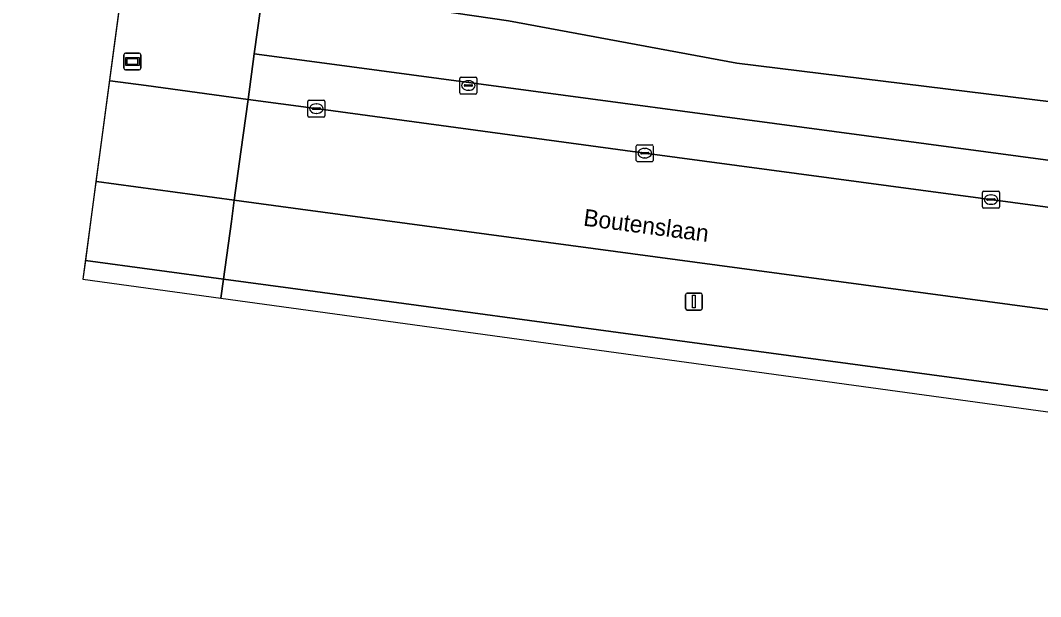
# Model space of a CAD drawing. Extents: x 161139 to 161601, y 381708 to 382245.
# Drawn here: x 161255.1 to 161315.4, y 381708.6 to 381742.6 of the extents above; entities that cross this region are included whole.
import ezdxf

# ---------------------------------------------------------------- set-up
doc = ezdxf.new("R2010")
doc.units = 0
for name, color, linetype in [('IMGEO_Berm_groen', 7, 'Continuous'), ('IMGEO_Dek', 7, 'Continuous'), ('IMGEO_Informatiebord', 7, 'Continuous'), ('IMGEO_Kolk', 7, 'Continuous'), ('IMGEO_Lichtmast', 7, 'Continuous'), ('IMGEO_Openbare_ruimte_label', 7, 'Continuous'), ('IMGEO_Rijbaan_regionaal_gesloten', 7, 'Continuous'), ('IMGEO_Rioolput', 7, 'Continuous'), ('IMGEO_Waterloop', 7, 'Continuous')]:
    doc.layers.add(name, color=color, linetype=linetype)

msp = doc.modelspace()

# ---------------------------------------------------------------- linework, layer by layer
at = {"layer": 'IMGEO_Berm_groen'}
for points in [[(161260.408, 381739.045), (161260.451, 381739.039), (161262.58, 381738.75), (161268.596, 381737.935), (161268.964, 381740.632), (161269.503, 381744.577), (161269.509, 381744.62), (161269.019, 381744.662), (161268.53, 381744.705), (161267.855, 381744.799), (161263.559, 381745.382), (161263.146, 381745.438), (161261.357, 381745.672), (161261.293, 381745.681)], [(161283.989, 381742.578), (161279.785, 381743.184), (161278.93, 381743.302), (161273.313, 381744.063), (161270.564, 381744.435), (161269.503, 381744.577), (161268.964, 381740.632), (161272.807, 381740.117), (161390.902, 381724.29), (161397.032, 381723.44), (161397.056, 381723.621), (161396.92, 381724.62), (161396.612, 381725.505), (161395.912, 381726.127), (161393.777, 381727.484), (161392.598, 381727.943), (161386.682, 381728.916), (161372.991, 381730.97), (161355.514, 381733.064), (161324.679, 381736.724), (161297.467, 381740.089)], [(161272.807, 381740.117), (161268.964, 381740.632), (161268.596, 381737.935), (161272.46, 381737.411), (161292.031, 381734.758), (161396.904, 381720.692), (161397.234, 381723.065), (161397.244, 381723.227), (161397.008, 381723.257), (161397.032, 381723.44), (161390.902, 381724.29)], [(161258.99, 381728.417), (161259, 381728.416), (161267.146, 381727.315), (161267.61, 381730.715), (161267.783, 381731.983), (161259.637, 381733.078), (161259.612, 381733.081)], [(161271.697, 381731.457), (161267.783, 381731.983), (161267.61, 381730.715), (161267.146, 381727.315), (161271.097, 381726.781), (161295.256, 381723.516), (161341.985, 381717.206), (161388.748, 381710.952), (161395.417, 381710.059), (161396.075, 381714.735)]]:
    msp.add_lwpolyline(points, close=True, dxfattribs=at)
msp.add_lwpolyline([(161269.509, 381744.62), (161269.503, 381744.577), (161270.564, 381744.435), (161273.313, 381744.063), (161278.93, 381743.302), (161279.785, 381743.184), (161283.989, 381742.578), (161297.467, 381740.089), (161324.679, 381736.724), (161355.514, 381733.064), (161372.991, 381730.97), (161386.682, 381728.916), (161392.598, 381727.943), (161393.777, 381727.484), (161395.912, 381726.127), (161396.612, 381725.505), (161396.92, 381724.62), (161397.056, 381723.621), (161397.032, 381723.44), (161397.008, 381723.257), (161397.244, 381723.227), (161397.255, 381723.409), (161401.979, 381722.847), (161404.437, 381741.198)], dxfattribs=at)
at = {"layer": 'IMGEO_Dek'}
msp.add_lwpolyline([(161266.992, 381726.19), (161267.146, 381727.315), (161267.61, 381730.715), (161267.783, 381731.983), (161268.174, 381734.839), (161268.596, 381737.935), (161268.964, 381740.632), (161269.503, 381744.577), (161270.244, 381750), (161270.446, 381751.48), (161270.863, 381754.533), (161270.924, 381754.975), (161262.781, 381756.092), (161262.685, 381756.105), (161258.842, 381727.311)], close=True, dxfattribs=at)
at = {"layer": 'IMGEO_Informatiebord'}
for p, q in [((161261.264, 381739.778), (161261.264, 381740.578)), ((161261.264, 381740.578), (161261.264, 381739.778)), ((161261.364, 381740.678), (161262.154, 381740.678)), ((161262.154, 381740.678), (161261.364, 381740.678)), ((161262.254, 381740.578), (161262.254, 381739.778)), ((161262.254, 381739.778), (161262.254, 381740.578)), ((161262.154, 381739.678), (161261.364, 381739.678)), ((161261.364, 381739.678), (161262.154, 381739.678))]:
    msp.add_line(p, q, dxfattribs=at)
for points in [[(161261.365, 381740.41), (161262.153, 381740.41), (161262.153, 381739.946), (161261.365, 381739.946), (161261.365, 381740.41)], [(161261.43, 381740.345), (161261.43, 381740.011), (161262.088, 381740.011), (161262.088, 381740.345), (161261.43, 381740.345)]]:
    msp.add_lwpolyline(points, dxfattribs=at)
for centre, start, end in [((161261.364, 381740.578), 90, 180), ((161261.364, 381740.578), 90, 180), ((161262.154, 381740.578), 0, 90), ((161262.154, 381740.578), 360, 90), ((161261.364, 381739.778), 180, 270), ((161261.364, 381739.778), 180, 270), ((161262.154, 381739.778), 270, 0), ((161262.154, 381739.778), 270, 0)]:
    msp.add_arc(centre, 0.1, start, end, dxfattribs=at)
at = {"layer": 'IMGEO_Kolk'}
for p, q in [((161272.131, 381736.967), (161272.131, 381737.819)), ((161272.206, 381737.893), (161273.058, 381737.893)), ((161272.619, 381737.673), (161272.644, 381737.673)), ((161273.132, 381737.819), (161273.132, 381736.967)), ((161273.058, 381736.893), (161272.206, 381736.893)), ((161272.39, 381737.387), (161272.39, 381737.399)), ((161272.828, 381737.35), (161272.43, 381737.35)), ((161272.433, 381737.436), (161272.831, 381737.436)), ((161272.642, 381737.113), (161272.617, 381737.113)), ((161272.874, 381737.399), (161272.874, 381737.387)), ((161291.53, 381734.332), (161291.53, 381735.184)), ((161291.605, 381735.258), (161292.457, 381735.258)), ((161292.531, 381735.184), (161292.531, 381734.332)), ((161291.789, 381734.752), (161291.789, 381734.764)), ((161292.227, 381734.715), (161291.829, 381734.715)), ((161291.832, 381734.801), (161292.23, 381734.801)), ((161292.041, 381734.478), (161292.016, 381734.478)), ((161292.018, 381735.038), (161292.043, 381735.038)), ((161292.273, 381734.764), (161292.273, 381734.752)), ((161292.457, 381734.258), (161291.605, 381734.258)), ((161311.983, 381731.591), (161311.983, 381732.443)), ((161312.058, 381732.517), (161312.91, 381732.517)), ((161312.285, 381732.06), (161312.683, 381732.06)), ((161312.471, 381732.297), (161312.496, 381732.297)), ((161312.984, 381732.443), (161312.984, 381731.591)), ((161312.91, 381731.517), (161312.058, 381731.517)), ((161312.242, 381732.011), (161312.242, 381732.023)), ((161312.68, 381731.974), (161312.282, 381731.974)), ((161312.494, 381731.737), (161312.469, 381731.737)), ((161312.726, 381732.023), (161312.726, 381732.011))]:
    msp.add_line(p, q, dxfattribs=at)
for points in [[(161272.131, 381736.967), (161272.131, 381737.819)], [(161272.206, 381737.893), (161273.058, 381737.893)], [(161273.132, 381737.819), (161273.132, 381736.967)], [(161273.058, 381736.893), (161272.206, 381736.893)], [(161291.53, 381734.332), (161291.53, 381735.184)], [(161291.605, 381735.258), (161292.457, 381735.258)], [(161292.531, 381735.184), (161292.531, 381734.332)], [(161292.457, 381734.258), (161291.605, 381734.258)], [(161311.983, 381731.591), (161311.983, 381732.443)], [(161312.058, 381732.517), (161312.91, 381732.517)], [(161312.984, 381732.443), (161312.984, 381731.591)], [(161312.91, 381731.517), (161312.058, 381731.517)]]:
    msp.add_lwpolyline(points, dxfattribs=at)
for centre, radius, start, end in [((161272.208, 381737.817), 0.0765, 91.55205, 178.44795), ((161272.208, 381737.817), 0.0765, 91.55205, 178.44795), ((161273.056, 381737.817), 0.0765, 1.55205, 88.44795), ((161273.056, 381737.817), 0.0765, 1.55205, 88.44795), ((161272.208, 381736.969), 0.0765, 181.55205, 268.44795), ((161272.208, 381736.969), 0.0765, 181.55205, 268.44795), ((161272.43, 381737.396), 0.0403, 85.87752, 175.75265), ((161272.427, 381737.386), 0.0366, 178.93798, 274.71019), ((161272.831, 381737.393), 0.043, 264.86636, 352.45326), ((161272.835, 381737.398), 0.0386, 1.73085, 96.63898), ((161273.056, 381736.969), 0.0765, 271.55205, 358.44795), ((161273.056, 381736.969), 0.0765, 271.55205, 358.44795), ((161291.607, 381735.182), 0.0765, 91.55205, 178.44795), ((161291.607, 381735.182), 0.0765, 91.55205, 178.44795), ((161292.455, 381735.182), 0.0765, 1.55205, 88.44795), ((161292.455, 381735.182), 0.0765, 1.55205, 88.44795), ((161291.829, 381734.761), 0.0403, 85.87752, 175.75265), ((161291.826, 381734.751), 0.0366, 178.93798, 274.71019), ((161292.23, 381734.758), 0.043, 264.86636, 352.45326), ((161292.234, 381734.763), 0.0386, 1.73085, 96.63898), ((161291.607, 381734.334), 0.0765, 181.55205, 268.44795), ((161291.607, 381734.334), 0.0765, 181.55205, 268.44795), ((161292.455, 381734.334), 0.0765, 271.55205, 358.44795), ((161292.455, 381734.334), 0.0765, 271.55205, 358.44795), ((161312.06, 381732.441), 0.0765, 91.55205, 178.44795), ((161312.06, 381732.441), 0.0765, 91.55205, 178.44795), ((161312.282, 381732.02), 0.0403, 85.87752, 175.75265), ((161312.687, 381732.022), 0.0386, 1.73085, 96.63898), ((161312.908, 381732.441), 0.0765, 1.55205, 88.44795), ((161312.908, 381732.441), 0.0765, 1.55205, 88.44795), ((161312.06, 381731.593), 0.0765, 181.55205, 268.44795), ((161312.06, 381731.593), 0.0765, 181.55205, 268.44795), ((161312.279, 381732.01), 0.0366, 178.93798, 274.71019), ((161312.683, 381732.017), 0.043, 264.86636, 352.45326), ((161312.908, 381731.593), 0.0765, 271.55205, 358.44795), ((161312.908, 381731.593), 0.0765, 271.55205, 358.44795)]:
    msp.add_arc(centre, radius, start, end, dxfattribs=at)
for centre, major_axis, ratio, start_param, end_param in [((161272.618, 381737.393), (-0.387, 0.002), 0.722429, 4.712389, 7.853982), ((161272.643, 381737.393), (-0.39, 0.002), 0.717154, 1.570796, 4.712389), ((161292.017, 381734.758), (-0.387, 0.002), 0.722429, 4.712389, 7.853982), ((161292.042, 381734.758), (-0.39, 0.002), 0.717154, 1.570796, 4.712389), ((161312.47, 381732.017), (-0.387, 0.002), 0.722429, 4.712389, 7.853982), ((161312.495, 381732.017), (-0.39, 0.002), 0.717154, 1.570796, 4.712389)]:
    msp.add_ellipse(centre, major_axis=major_axis, ratio=ratio, start_param=start_param, end_param=end_param, dxfattribs=at)
at = {"layer": 'IMGEO_Lichtmast'}
for p, q in [((161294.437, 381725.589), (161294.437, 381726.389)), ((161294.437, 381726.389), (161294.437, 381725.589)), ((161294.537, 381726.489), (161295.327, 381726.489)), ((161295.327, 381726.489), (161294.537, 381726.489)), ((161295.427, 381726.389), (161295.427, 381725.589)), ((161295.427, 381725.589), (161295.427, 381726.389)), ((161295.327, 381725.489), (161294.537, 381725.489)), ((161294.537, 381725.489), (161295.327, 381725.489))]:
    msp.add_line(p, q, dxfattribs=at)
msp.add_lwpolyline([(161294.857, 381726.364), (161295.007, 381726.364), (161295.007, 381725.614), (161294.857, 381725.614), (161294.857, 381726.364)], dxfattribs=at)
for centre, start, end in [((161294.537, 381726.389), 90, 180), ((161294.537, 381726.389), 90, 180), ((161295.327, 381726.389), 0, 90), ((161295.327, 381726.389), 360, 90), ((161294.537, 381725.589), 180, 270), ((161294.537, 381725.589), 180, 270), ((161295.327, 381725.589), 270, 0), ((161295.327, 381725.589), 270, 0)]:
    msp.add_arc(centre, 0.1, start, end, dxfattribs=at)
at = {"layer": 'IMGEO_Rijbaan_regionaal_gesloten'}
for points in [[(161260.408, 381739.045), (161259.612, 381733.081), (161259.637, 381733.078), (161267.783, 381731.983), (161268.174, 381734.839), (161268.596, 381737.935), (161262.58, 381738.75), (161260.451, 381739.039)], [(161292.031, 381734.758), (161272.46, 381737.411), (161268.596, 381737.935), (161268.174, 381734.839), (161267.783, 381731.983), (161271.697, 381731.457), (161396.075, 381714.735), (161396.904, 381720.692)], [(161258.99, 381728.417), (161258.842, 381727.311), (161266.992, 381726.19), (161267.146, 381727.315), (161259, 381728.416)], [(161395.21, 381708.555), (161395.417, 381710.059), (161388.748, 381710.952), (161341.985, 381717.206), (161295.256, 381723.516), (161271.097, 381726.781), (161267.146, 381727.315), (161266.992, 381726.19)]]:
    msp.add_lwpolyline(points, close=True, dxfattribs=at)
at = {"layer": 'IMGEO_Rioolput'}
for p, q in [((161281.11, 381738.33), (161281.11, 381739.182)), ((161281.185, 381739.256), (161282.037, 381739.256)), ((161281.369, 381738.75), (161281.369, 381738.762)), ((161281.807, 381738.713), (161281.409, 381738.713)), ((161281.412, 381738.799), (161281.81, 381738.799)), ((161281.598, 381739.036), (161281.623, 381739.036)), ((161281.853, 381738.762), (161281.853, 381738.75)), ((161282.111, 381739.182), (161282.111, 381738.33)), ((161282.037, 381738.256), (161281.185, 381738.256)), ((161281.621, 381738.476), (161281.596, 381738.476))]:
    msp.add_line(p, q, dxfattribs=at)
for points in [[(161281.11, 381738.33), (161281.11, 381739.182)], [(161281.185, 381739.256), (161282.037, 381739.256)], [(161282.111, 381739.182), (161282.111, 381738.33)], [(161282.037, 381738.256), (161281.185, 381738.256)]]:
    msp.add_lwpolyline(points, dxfattribs=at)
for centre, radius, start, end in [((161281.187, 381739.18), 0.0765, 91.55205, 178.44795), ((161281.187, 381739.18), 0.0765, 91.55205, 178.44795), ((161281.409, 381738.759), 0.0403, 85.87752, 175.75265), ((161281.406, 381738.749), 0.0366, 178.93798, 274.71019), ((161281.81, 381738.756), 0.043, 264.86636, 352.45326), ((161281.814, 381738.761), 0.0386, 1.73085, 96.63898), ((161282.035, 381739.18), 0.0765, 1.55205, 88.44795), ((161282.035, 381739.18), 0.0765, 1.55205, 88.44795), ((161281.187, 381738.332), 0.0765, 181.55205, 268.44795), ((161281.187, 381738.332), 0.0765, 181.55205, 268.44795), ((161282.035, 381738.332), 0.0765, 271.55205, 358.44795), ((161282.035, 381738.332), 0.0765, 271.55205, 358.44795)]:
    msp.add_arc(centre, radius, start, end, dxfattribs=at)
for centre, major_axis, ratio, start_param, end_param in [((161281.597, 381738.756), (-0.387, 0.002), 0.722429, 4.712389, 7.853982), ((161281.622, 381738.756), (-0.39, 0.002), 0.717154, 1.570796, 4.712389)]:
    msp.add_ellipse(centre, major_axis=major_axis, ratio=ratio, start_param=start_param, end_param=end_param, dxfattribs=at)
at = {"layer": 'IMGEO_Waterloop'}
msp.add_lwpolyline([(161154.01, 381930.315), (161154.01, 381900.309), (161139.589, 381880.498), (161142.478, 381862.176), (161175.165, 381814.484), (161259.316, 381777.572), (161264.288, 381768.121), (161258.842, 381727.311), (161266.992, 381726.19), (161267.146, 381727.315), (161267.61, 381730.715), (161267.783, 381731.983), (161268.174, 381734.839), (161268.596, 381737.935), (161268.964, 381740.632), (161269.503, 381744.577), (161269.509, 381744.62), (161270.244, 381750), (161270.446, 381751.48), (161270.863, 381754.533), (161270.924, 381754.975), (161271.183, 381756.434)], dxfattribs=at)

# ---------------------------------------------------------------- texts
at = {"layer": 'IMGEO_Openbare_ruimte_label'}
msp.add_text('Boutenslaan', height=1, rotation=352.52658, dxfattribs=at).set_placement((161288.366, 381730.483))

doc.saveas('drawing.dxf')
